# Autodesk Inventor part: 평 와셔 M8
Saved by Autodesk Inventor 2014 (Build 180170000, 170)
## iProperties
Created: 2026-09
Part Number: 평 와셔 M8
Material: 일반
Document SubType Name: Modeling
Designer: dg
Density: 1 g/cm^3
Appearance: 기본값
Author: dg
Author: jhkim
Description: 평면 와셔
Creation Date: 2026-08-27
Sending System: Autodesk Inventor 2027
Preprocessor: ST-DEVELOPER v20.1
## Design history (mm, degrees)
node "평 와셔 M81"
body "Solid1"
node "기준1"
